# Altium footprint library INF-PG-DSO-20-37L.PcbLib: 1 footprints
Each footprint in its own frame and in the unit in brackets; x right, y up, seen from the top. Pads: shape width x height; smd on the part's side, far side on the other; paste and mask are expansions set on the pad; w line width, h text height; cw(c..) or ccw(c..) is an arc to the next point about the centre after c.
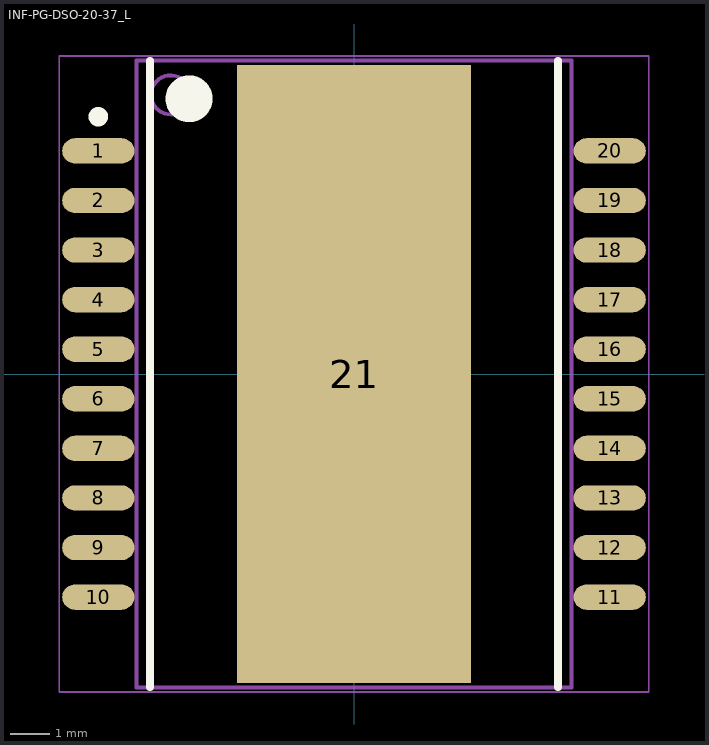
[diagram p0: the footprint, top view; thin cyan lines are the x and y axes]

## INF-PG-DSO-20-37_L [mm] "SOP, 20-Leads, Body 15.9x11mm, Pitch 1.27mm, Thermal Pad 15.84x6mm, IPC High Density"
height 3.5
pads (21):
  oval 1.85x0.65 smd: 1(-6.55,5.715) 2(-6.55,4.445) 3(-6.55,3.175) 4(-6.55,1.905) 5(-6.55,0.635) 6(-6.55,-0.635) 7(-6.55,-1.905) 8(-6.55,-3.175) 9(-6.55,-4.445) 10(-6.55,-5.715) 11(6.55,-5.715) 12(6.55,-4.445) 13(6.55,-3.175) 14(6.55,-1.905) 15(6.55,-0.635) 16(6.55,0.635) 17(6.55,1.905) 18(6.55,3.175) 19(6.55,4.445) 20(6.55,5.715)
  rect 6x15.84 smd: 21(0,0)
Top Overlay:
  circle w0.6: c-4.225,7.05 r0.3
  circle w0.25: c-6.55,6.59 r0.125
  lines w0.2: -5.225,-8.025 -5.225,8.025 ; 5.225,-8.025 5.225,8.025
Mechanical 13:
  circle w0.1: c-4.7,7.15 r0.5
  lines w0.1: -5.575,-8.025 5.575,-8.025 5.575,8.025 -5.575,8.025 -5.575,-8.025
Mechanical 15:
  lines w0.05: -7.55,-8.15 7.55,-8.15 7.55,8.15 -7.55,8.15 -7.55,-8.15
  lines w0.1: -0.5,0 0.5,0 ; 0,-0.5 0,0.5
3D body: height 3.5, standoff 0, extent -5.575,-8.025 5.575,8.025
